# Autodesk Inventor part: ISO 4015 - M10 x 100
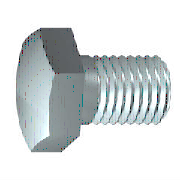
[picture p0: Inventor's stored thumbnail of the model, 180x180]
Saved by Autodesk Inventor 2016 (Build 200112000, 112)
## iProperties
IsCustomPart: 0
Created: 2013-09
Part Number: ISO 4015 - M10 x 100
Material: Stainless Steel, 440C
Description: HEX BOLT ISO M10 x 100 SST
Document SubType Name: Modeling
Standard: ISO 4015
Designer: normanpa
Standard Revision: First edition 1979-07-01
Standards Organization: ISO
Language: en-US
Size Designation: M10 x 100
Categories: <MemberInstance><Categories><Category DisplayName="Fasteners" InternalName="e4da775c-781d-43d5-af7c-5136215cf5a6" Mnemonic="FSTN"><Category DisplayName="Bolts"
Density: 7.75 g/cm^3
Appearance: Semi-Polished
Author: normanpa
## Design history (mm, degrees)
sketch "Sketch2"
  geometry: L1 (0, 63.511)-(0, -36.489); L2 (0, -36.489)-(4.25, -36.489); L3 (5, -35.739)-(5, -10.489); L4 (5, -10.489)-(4.45, -9.536); L5 (4.45, -9.536)-(4.45, 63.511); L6 (4.45, 63.511)-(0, 63.511); L7 (4.25, -36.489)-(5, -35.739); L8 (5, -36.489)-(5, -37.55); L9 (0, -57.762)-(0, 83.723) reference; 1 further point
  constraints: 16 end point, 3 parallel, 2 collinear, 2 perpendicular, 2 point on line, 1 equal length, 1 horizontal alignment, 1 vertical
  dimensions: "Ds" = 8.9 diameter of L5 L1; "NND" = 10 diameter of L3 L1; "b" = 26 distance of point (5, -36.489) L3.end; "d3" = 30 deg angle of L3 L4; "d5" = 45 deg angle of L2 L7; "PTC" = 1.5 diameter of L2.end L8; "NLG" = 100 distance of L1.start L1.end
revolve "Revolution1" sketch "Sketch2" stored, may be unused: angle "d8" = 90 deg
sketch "Sketch3"
  geometry: L1 (0, 8)-(4.619, 8); L2 (4.619, 8)-(9.238, 0); L3 (9.238, 0)-(0, 0); L4 (0, 0)-(0, 8); L5 (-4.619, 8)-(-9.238, 0); L6 (0, 8)-(-4.619, 8); L7 (-4.619, -8)-(-9.238, 0); L8 (0, -8)-(-4.619, -8); L9 (0, -8)-(4.619, -8); L10 (4.619, -8)-(9.238, 0); C1 r 4.45 at (0, 0) reference
  constraints: 20 end point, 5 symmetric about line, 1 horizontal, 1 parallel, 1 perpendicular, 6 other
  dimensions: "d9" = 60 deg angle of L3 L2; "ParS" = 16 distance of L9.end L1.end; "msp_d11" = 16 distance between parallel lines of L10 L5 (= ParS)
extrude "Extrusion1" join sketch "Sketch3" taper "d13" = 0 deg; distance "ParK" = 6.4
sketch "Sketch4"
  geometry: L1 (-8, 69.911)-(-9.238, 69.911); L2 (-9.238, 69.911)-(-9.238, 69.196); L3 (-9.238, 69.196)-(-8, 69.911); L4 (0, 18.632)-(0, 78.457) reference; L5 (0, 27.893)-(0, 27.179); L6 (-9.238, 63.511)-(-9.238, 69.911) reference; L7 (-4.619, 69.911)-(-9.238, 69.911) reference
  constraints: 8 end point, 4 collinear, 1 horizontal, 1 parallel, 1 perpendicular
  dimensions: "d14" = 30 deg angle of L3 L1; "msp_d15" = 16 diameter of L1.start L5 (= ParS)
revolve "Revolution2" sketch "Sketch4" stored, may be unused: angle "d16" = 90 deg
sketch "Sketch5"
  geometry: C1 r 6 at (0, 0); A1 r 8 centre (0, 0) between (6.928, 4) and (0, 8) reference
  constraints: 1 centre point, 1 coincident
  dimensions: "d27" = 12 diameter of C1 (= 0.75 x ParS)
extrude "Extrusion2" cut sketch "Sketch5" distance "d28" = 1.28 (= 0.2 x ParK); taper "d29" = 0 deg
node "MSC_A1"
node "MSC_PF1"
node "MSC_PT1"
fillet "Fillet1" dims "d30" = 0.4 (= r)
body "Solid1"
thread "Thread1" dims "d18" = 0, "msp_d17" = 26 (= b)
other parameters: "d22" = 0, "d23" = 0, "d25" = 0, "d26" = 0, "r" = 0.4 [user parameter; used in 1 equation term], "d31" = 0
